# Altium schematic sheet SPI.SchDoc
size A4
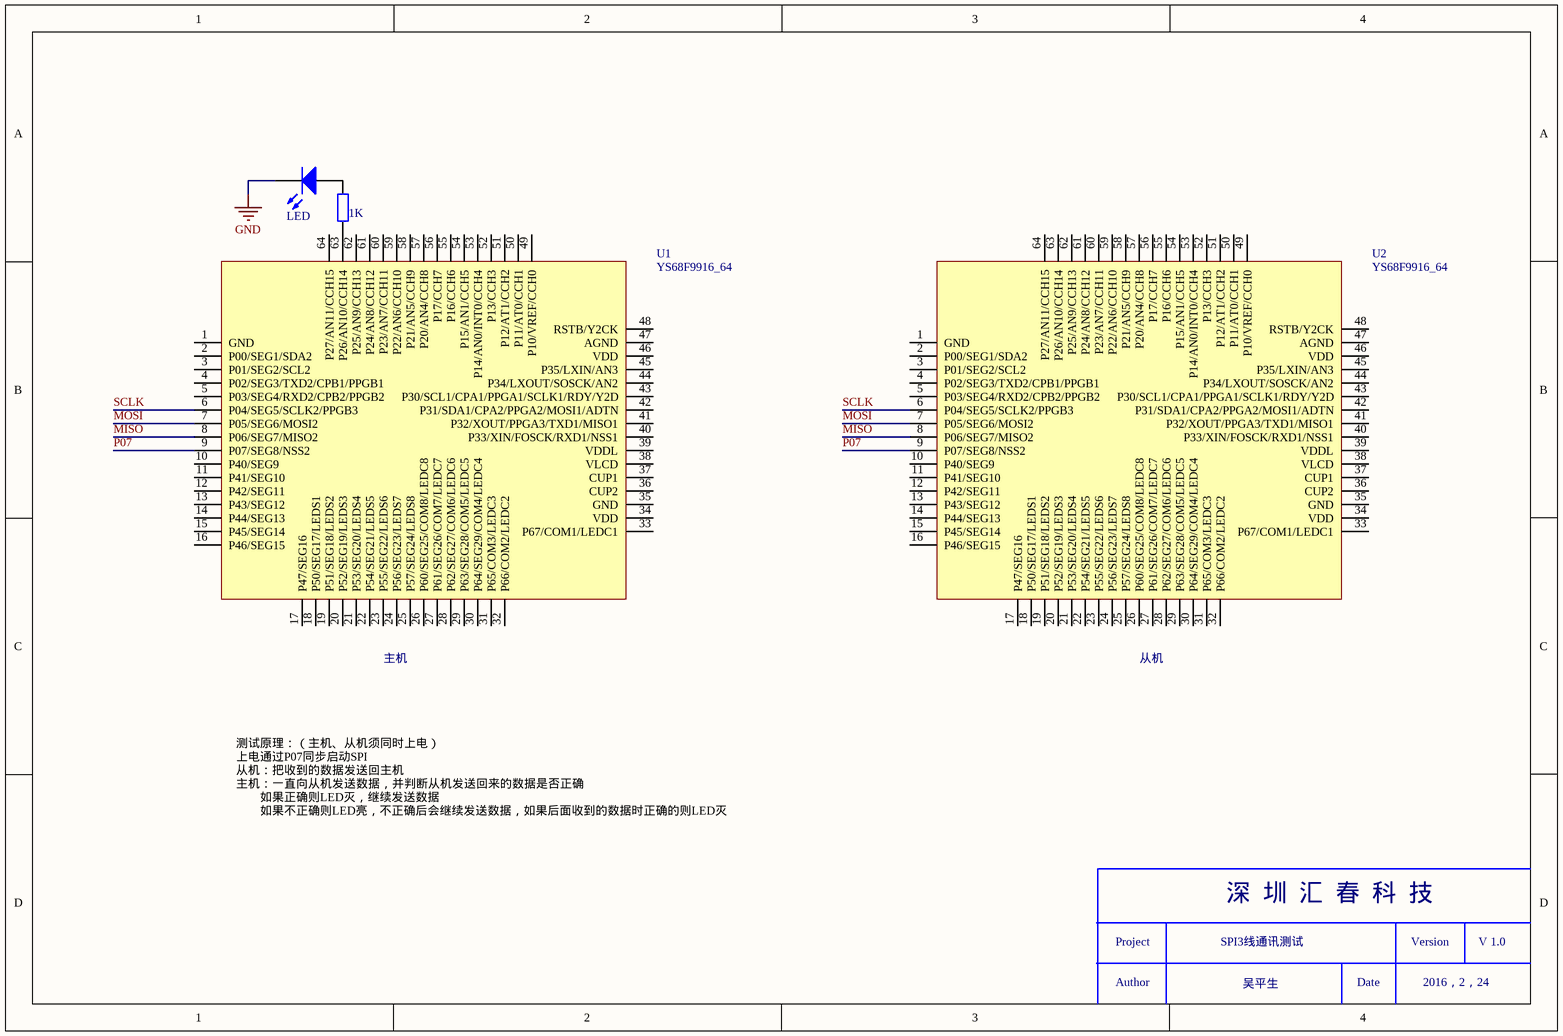
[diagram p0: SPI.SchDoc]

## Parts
DS?  LED  [LED-0]
R?  value 1K  [AXIAL-0.4]  (hidden comment: Res2)
U1  YS68F9916_64
U2  YS68F9916_64

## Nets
GND: DS?.2(K)
MISO: U1.8(P06/SEG7/MISO2) U2.8(P06/SEG7/MISO2)
MOSI: U1.7(P05/SEG6/MOSI2) U2.7(P05/SEG6/MOSI2)
P07: U1.9(P07/SEG8/NSS2) U2.9(P07/SEG8/NSS2)
SCLK: U1.6(P04/SEG5/SCLK2/PPGB3) U2.6(P04/SEG5/SCLK2/PPGB3)
NetDS?_1: DS?.1(A) R?.2
NetR?_1: R?.1 U1.63(P26/AN10/CCH14)

Not connected (* = marked no-connect by the designer): U1 1(GND) 2(P00/SEG1/SDA2) 3(P01/SEG2/SCL2) 4(P02/SEG3/TXD2/CPB1/PPGB1) 5(P03/SEG4/RXD2/CPB2/PPGB2) 10(P40/SEG9) 11(P41/SEG10) 12(P42/SEG11) 13(P43/SEG12) 14(P44/SEG13) 15(P45/SEG14) 16(P46/SEG15) 17(P47/SEG16) 18(P50/SEG17/LEDS1) 19(P51/SEG18/LEDS2) 20(P52/SEG19/LEDS3) 21(P53/SEG20/LEDS4) 22(P54/SEG21/LEDS5) 23(P55/SEG22/LEDS6) 24(P56/SEG23/LEDS7) 25(P57/SEG24/LEDS8) 26(P60/SEG25/COM8/LEDC8) 27(P61/SEG26/COM7/LEDC7) 28(P62/SEG27/COM6/LEDC6) 29(P63/SEG28/COM5/LEDC5) 30(P64/SEG29/COM4/LEDC4) 31(P65/COM3/LEDC3) 32(P66/COM2/LEDC2) 33(P67/COM1/LEDC1) 34(VDD) 35(GND) 36(CUP2) 37(CUP1) 38(VLCD) 39(VDDL) 40(P33/XIN/FOSCK/RXD1/NSS1) 41(P32/XOUT/PPGA3/TXD1/MISO1) 42(P31/SDA1/CPA2/PPGA2/MOSI1/ADTN) 43(P30/SCL1/CPA1/PPGA1/SCLK1/RDY/Y2D) 44(P34/LXOUT/SOSCK/AN2) 45(P35/LXIN/AN3) 46(VDD) 47(AGND) 48(RSTB/Y2CK) 49(P10/VREF/CCH0) 50(P11/AT0/CCH1) 51(P12/AT1/CCH2) 52(P13/CCH3) 53(P14/AN0/INT0/CCH4) 54(P15/AN1/CCH5) 55(P16/CCH6) 56(P17/CCH7) 57(P20/AN4/CCH8) 58(P21/AN5/CCH9) 59(P22/AN6/CCH10) 60(P23/AN7/CCH11) 61(P24/AN8/CCH12) 62(P25/AN9/CCH13) 64(P27/AN11/CCH15); U2 1(GND) 2(P00/SEG1/SDA2) 3(P01/SEG2/SCL2) 4(P02/SEG3/TXD2/CPB1/PPGB1) 5(P03/SEG4/RXD2/CPB2/PPGB2) 10(P40/SEG9) 11(P41/SEG10) 12(P42/SEG11) 13(P43/SEG12) 14(P44/SEG13) 15(P45/SEG14) 16(P46/SEG15) 17(P47/SEG16) 18(P50/SEG17/LEDS1) 19(P51/SEG18/LEDS2) 20(P52/SEG19/LEDS3) 21(P53/SEG20/LEDS4) 22(P54/SEG21/LEDS5) 23(P55/SEG22/LEDS6) 24(P56/SEG23/LEDS7) 25(P57/SEG24/LEDS8) 26(P60/SEG25/COM8/LEDC8) 27(P61/SEG26/COM7/LEDC7) 28(P62/SEG27/COM6/LEDC6) 29(P63/SEG28/COM5/LEDC5) 30(P64/SEG29/COM4/LEDC4) 31(P65/COM3/LEDC3) 32(P66/COM2/LEDC2) 33(P67/COM1/LEDC1) 34(VDD) 35(GND) 36(CUP2) 37(CUP1) 38(VLCD) 39(VDDL) 40(P33/XIN/FOSCK/RXD1/NSS1) 41(P32/XOUT/PPGA3/TXD1/MISO1) 42(P31/SDA1/CPA2/PPGA2/MOSI1/ADTN) 43(P30/SCL1/CPA1/PPGA1/SCLK1/RDY/Y2D) 44(P34/LXOUT/SOSCK/AN2) 45(P35/LXIN/AN3) 46(VDD) 47(AGND) 48(RSTB/Y2CK) 49(P10/VREF/CCH0) 50(P11/AT0/CCH1) 51(P12/AT1/CCH2) 52(P13/CCH3) 53(P14/AN0/INT0/CCH4) 54(P15/AN1/CCH5) 55(P16/CCH6) 56(P17/CCH7) 57(P20/AN4/CCH8) 58(P21/AN5/CCH9) 59(P22/AN6/CCH10) 60(P23/AN7/CCH11) 61(P24/AN8/CCH12) 62(P25/AN9/CCH13) 63(P26/AN10/CCH14) 64(P27/AN11/CCH15)

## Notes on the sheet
- 主机
- 从机
- 测试原理：（主机、从机须同时上电）
  上电通过P07同步启动SPI
  从机：把收到的数据发送回主机
  主机：一直向从机发送数据，并判断从机发送回来的数据是否正确
  如果正确则LED灭，继续发送数据
  如果不正确则LED亮，不正确后会继续发送数据，如果后面收到的数据时正确的则LED灭
- SPI3线通讯测试
- 2016，2，24
- 1.0

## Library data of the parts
DS? = LED0: Typical INFRARED GaAs LED
R? = Res2: Resistor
